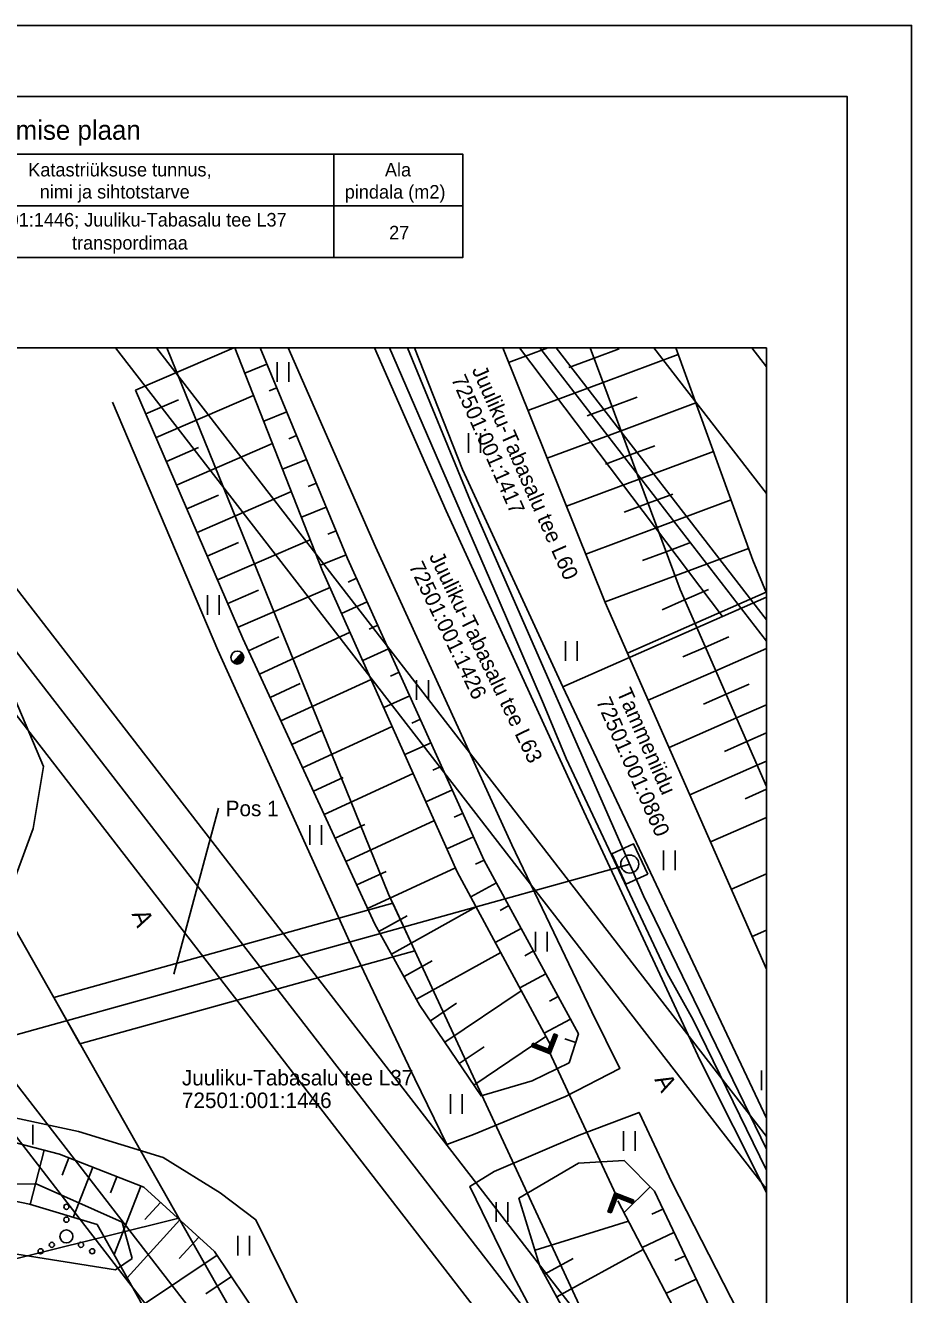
# Model space of a CAD drawing. Extents: x 533279.3 to 533331.8, y 6581483.1 to 6581557.3.
# Drawn here: x 533297.45 to 533331.79, y 6581508.13 to 6581557.32 of the extents above; entities that cross this region are included whole.
import ezdxf

# ---------------------------------------------------------------- set-up
doc = ezdxf.new("R2010")
doc.units = 0
for name, color, linetype in [('HALJASTUS', 7, 'Continuous'), ('KASUTUSALA', 7, 'Continuous'), ('MPKAABEL', 7, 'Continuous'), ('PIIR', 7, 'Continuous'), ('POST', 7, 'Continuous'), ('PR_SIDE', 7, 'Continuous'), ('RELJEEF', 7, 'Continuous'), ('RP-nõlv', 7, 'Continuous'), ('RP-tee_servajoon', 7, 'Continuous'), ('RP-telg_tee', 7, 'Continuous'), ('SITRASS', 7, 'Continuous'), ('TEE', 7, 'Continuous'), ('TRUUP', 7, 'Continuous'), ('VORMISTUS', 7, 'Continuous')]:
    doc.layers.add(name, color=color, linetype=linetype)

msp = doc.modelspace()

# ---------------------------------------------------------------- linework, layer by layer
at = {"layer": 'HALJASTUS'}
for p, q in [((533307.211, 6581544.271), (533307.211, 6581543.51)), ((533307.666, 6581544.271), (533307.666, 6581543.51)), ((533314.628, 6581541.515), (533314.628, 6581540.754)), ((533315.083, 6581541.515), (533315.083, 6581540.754)), ((533304.51, 6581535.234), (533304.51, 6581534.473)), ((533304.966, 6581535.234), (533304.966, 6581534.473)), ((533318.384, 6581533.45), (533318.384, 6581532.689)), ((533318.839, 6581533.45), (533318.839, 6581532.689)), ((533312.613, 6581531.94), (533312.613, 6581531.179)), ((533313.068, 6581531.94), (533313.068, 6581531.179)), ((533308.477, 6581526.324), (533308.477, 6581525.563)), ((533308.932, 6581526.324), (533308.932, 6581525.563)), ((533322.182, 6581525.342), (533322.182, 6581524.581)), ((533322.637, 6581525.342), (533322.637, 6581524.581)), ((533317.213, 6581522.185), (533317.213, 6581521.424)), ((533317.668, 6581522.185), (533317.668, 6581521.424)), ((533325.98, 6581516.812), (533325.98, 6581516.051)), ((533313.921, 6581515.893), (533313.921, 6581515.132)), ((533314.376, 6581515.893), (533314.376, 6581515.132)), ((533297.739, 6581514.711), (533297.739, 6581513.95)), ((533320.631, 6581514.458), (533320.631, 6581513.697)), ((533321.086, 6581514.458), (533321.086, 6581513.697)), ((533315.693, 6581511.713), (533315.693, 6581510.952)), ((533316.148, 6581511.713), (533316.148, 6581510.952)), ((533305.681, 6581510.404), (533305.681, 6581509.643)), ((533306.137, 6581510.404), (533306.137, 6581509.643))]:
    msp.add_line(p, q, dxfattribs=at)
msp.add_lwpolyline([(533301.596, 6581509.531), (533301.205, 6581510.943), (533297.872, 6581512.419), (533293.85, 6581512.397), (533292.416, 6581511.385), (533293.032, 6581509.744), (533296.798, 6581509.751), (533300.946, 6581509.084), (533301.596, 6581509.531)], dxfattribs=at)
for centre, radius in [((533299.042, 6581511.534), 0.1), ((533299.042, 6581511.034), 0.1), ((533299.042, 6581510.384), 0.25), ((533298.477, 6581510.059), 0.1), ((533299.607, 6581510.059), 0.1), ((533298.042, 6581509.809), 0.1), ((533300.042, 6581509.809), 0.1)]:
    msp.add_circle(centre, radius, dxfattribs=at)
at = {"layer": 'KASUTUSALA'}
msp.add_lwpolyline([(533311.685, 6581523.295), (533312.538, 6581521.458), (533299.566, 6581517.847), (533298.55, 6581519.64)], close=True, dxfattribs=at)
at = {"layer": 'MPKAABEL'}
msp.add_lwpolyline([(533311.563, 6581544.821), (533315.768, 6581535.104), (533317.532, 6581531.021), (533318.413, 6581528.914), (533322.317, 6581520.59), (533323.335, 6581518.773), (533326.169, 6581512.95)], dxfattribs=at)
at = {"layer": 'PIIR'}
for points in [[(533314.039, 6581492.321), (533303.4, 6581511.09), (533294.3, 6581527.13), (533291.41, 6581534.01), (533286.879, 6581544.821)], [(533326.169, 6581494.414), (533319, 6581507.54), (533311.52, 6581523.65), (533302.938, 6581544.821)], [(533302.938, 6581544.821), (533311.52, 6581523.65), (533319, 6581507.54), (533326.169, 6581494.414)], [(533316.594, 6581544.821), (533324.47, 6581534.41), (533318.28, 6581531.69), (533314.39, 6581540.11), (533312.531, 6581544.821)], [(533312.531, 6581544.821), (533314.39, 6581540.11), (533318.28, 6581531.69), (533326.169, 6581514.964)], [(533326.169, 6581535.157), (533324.47, 6581534.41), (533316.594, 6581544.821)], [(533326.169, 6581535.157), (533324.47, 6581534.41), (533318.28, 6581531.69), (533326.169, 6581514.964)], [(533284.919, 6581532.5), (533291.41, 6581534.01), (533294.3, 6581527.13), (533303.4, 6581511.09), (533289.68, 6581507.68), (533284.919, 6581513.462)], [(533301.868, 6581492.321), (533289.68, 6581507.68), (533303.4, 6581511.09), (533314.039, 6581492.321)]]:
    msp.add_lwpolyline(points, dxfattribs=at)
at = {"layer": 'POST'}
msp.add_line((533305.487, 6581532.643), (533305.84, 6581532.997), dxfattribs=at)
msp.add_circle((533305.664, 6581532.82), 0.25, dxfattribs=at)
for radius, start, end in [(0.225, 224.8541, 45.0356), (0.2, 224.8427, 45.047), (0.175, 224.8281, 45.0616), (0.15, 224.8087, 45.081), (0.125, 224.7814, 45.1083), (0.1, 224.7406, 45.1491), (0.075, 224.6725, 45.2172), (0.05, 224.5363, 45.3534), (0.025, 224.1278, 45.7619)]:
    msp.add_arc((533305.664, 6581532.82), radius, start, end, dxfattribs=at)
at = {"layer": 'PR_SIDE'}
msp.add_line((533284.919, 6581514.808), (533320.872, 6581524.815), dxfattribs=at)
msp.add_lwpolyline([(533321.567, 6581524.419), (533321.023, 6581525.6), (533320.178, 6581525.212), (533320.722, 6581524.031)], close=True, dxfattribs=at)
msp.add_circle((533320.872, 6581524.815), 0.35, dxfattribs=at)
at = {"layer": 'RELJEEF'}
for p, q in [((533301.723, 6581543.178), (533305.525, 6581544.821)), ((533317.696, 6581544.821), (533316.178, 6581544.257)), ((533319.488, 6581544.421), (533320.463, 6581544.784)), ((533319.837, 6581543.484), (533322.753, 6581544.569)), ((533306.813, 6581544.197), (533305.955, 6581543.841)), ((533319.488, 6581544.421), (533318.509, 6581544.057)), ((533307.196, 6581543.273), (533306.905, 6581543.152)), ((533319.837, 6581543.484), (533316.925, 6581542.401)), ((533302.12, 6581542.26), (533303.39, 6581542.809)), ((533302.517, 6581541.343), (533306.295, 6581542.976)), ((533320.185, 6581542.547), (533319.223, 6581542.189)), ((533320.185, 6581542.547), (533321.155, 6581542.907)), ((533320.534, 6581541.609), (533323.434, 6581542.688)), ((533307.579, 6581542.349), (533306.687, 6581541.979)), ((533320.534, 6581541.609), (533317.673, 6581540.545)), ((533303.31, 6581539.507), (533307.028, 6581541.114)), ((533307.963, 6581541.426), (533307.66, 6581541.3)), ((533302.914, 6581540.425), (533304.163, 6581540.965)), ((533320.883, 6581540.672), (533319.937, 6581540.32)), ((533320.883, 6581540.672), (533321.847, 6581541.031)), ((533321.231, 6581539.735), (533324.115, 6581540.808)), ((533308.346, 6581540.502), (533307.42, 6581540.118)), ((533308.729, 6581539.578), (533308.414, 6581539.448)), ((533321.231, 6581539.735), (533318.42, 6581538.689)), ((533303.707, 6581538.589), (533304.936, 6581539.12)), ((533304.104, 6581537.671), (533307.761, 6581539.251)), ((533321.58, 6581538.798), (533322.539, 6581539.154)), ((533309.112, 6581538.654), (533308.152, 6581538.256)), ((533321.58, 6581538.798), (533320.651, 6581538.452)), ((533321.929, 6581537.86), (533324.796, 6581538.927)), ((533309.495, 6581537.731), (533309.169, 6581537.596)), ((533321.929, 6581537.86), (533319.168, 6581536.833)), ((533304.5, 6581536.753), (533305.709, 6581537.275)), ((533304.897, 6581535.835), (533308.493, 6581537.389)), ((533322.277, 6581536.923), (533323.23, 6581537.278)), ((533309.878, 6581536.807), (533308.884, 6581536.395)), ((533322.277, 6581536.923), (533321.365, 6581536.584)), ((533322.626, 6581535.986), (533325.477, 6581537.047)), ((533310.286, 6581535.894), (533309.957, 6581535.745)), ((533322.626, 6581535.986), (533319.915, 6581534.977)), ((533305.294, 6581534.917), (533306.482, 6581535.431)), ((533305.691, 6581533.999), (533309.257, 6581535.54)), ((533322.998, 6581535.058), (533323.923, 6581535.464)), ((533323.399, 6581534.142), (533326.157, 6581535.351)), ((533310.698, 6581534.983), (533309.707, 6581534.534)), ((533322.998, 6581535.058), (533322.126, 6581534.676)), ((533306.518, 6581532.179), (533310.034, 6581533.802)), ((533311.111, 6581534.072), (533310.779, 6581533.922)), ((533323.399, 6581534.142), (533320.785, 6581532.996)), ((533306.099, 6581533.086), (533307.275, 6581533.629)), ((533323.801, 6581533.226), (533322.93, 6581532.844)), ((533323.801, 6581533.226), (533324.714, 6581533.627)), ((533311.523, 6581533.161), (533310.523, 6581532.708)), ((533324.202, 6581532.31), (533326.169, 6581533.172)), ((533311.936, 6581532.25), (533311.601, 6581532.099)), ((533324.202, 6581532.31), (533321.59, 6581531.165)), ((533306.938, 6581531.271), (533308.106, 6581531.81)), ((533307.357, 6581530.363), (533310.85, 6581531.976)), ((533324.604, 6581531.395), (533325.505, 6581531.79)), ((533312.348, 6581531.339), (533311.34, 6581530.883)), ((533324.604, 6581531.395), (533323.733, 6581531.013)), ((533325.005, 6581530.479), (533326.169, 6581530.989)), ((533312.761, 6581530.428), (533312.423, 6581530.275)), ((533325.005, 6581530.479), (533322.395, 6581529.334)), ((533307.776, 6581529.455), (533308.937, 6581529.991)), ((533308.196, 6581528.547), (533311.667, 6581530.15)), ((533325.407, 6581529.563), (533326.169, 6581529.897)), ((533313.173, 6581529.517), (533312.156, 6581529.057)), ((533325.407, 6581529.563), (533324.537, 6581529.181)), ((533325.808, 6581528.647), (533326.169, 6581528.805)), ((533309.034, 6581526.731), (533312.484, 6581528.325)), ((533313.585, 6581528.606), (533313.245, 6581528.452)), ((533325.808, 6581528.647), (533323.199, 6581527.503)), ((533308.615, 6581527.639), (533309.768, 6581528.172)), ((533313.998, 6581527.695), (533312.973, 6581527.231)), ((533326.169, 6581527.713), (533325.34, 6581527.35)), ((533309.454, 6581525.824), (533310.6, 6581526.353)), ((533309.873, 6581524.916), (533313.3, 6581526.499)), ((533314.41, 6581526.784), (533314.067, 6581526.629)), ((533326.169, 6581526.621), (533324.004, 6581525.672)), ((533314.823, 6581525.873), (533313.789, 6581525.405)), ((533326.169, 6581525.529), (533326.144, 6581525.519)), ((533315.235, 6581524.962), (533314.89, 6581524.806)), ((533310.292, 6581524.008), (533311.431, 6581524.534)), ((533310.711, 6581523.1), (533314.117, 6581524.673)), ((533326.169, 6581524.438), (533324.809, 6581523.841)), ((533315.712, 6581524.083), (533314.712, 6581523.541)), ((533311.638, 6581521.329), (533314.921, 6581523.154)), ((533316.189, 6581523.204), (533315.855, 6581523.023)), ((533311.153, 6581522.203), (533312.251, 6581522.814)), ((533316.666, 6581522.325), (533315.661, 6581521.78)), ((533326.169, 6581522.254), (533325.613, 6581522.01)), ((533312.61, 6581519.581), (533315.87, 6581521.393)), ((533317.143, 6581521.447), (533316.807, 6581521.264)), ((533312.124, 6581520.455), (533313.215, 6581521.061)), ((533317.62, 6581520.568), (533316.61, 6581520.019)), ((533313.708, 6581517.91), (533316.67, 6581519.907)), ((533313.149, 6581518.74), (533314.164, 6581519.423)), ((533318.097, 6581519.689), (533317.759, 6581519.505)), ((533318.574, 6581518.81), (533317.558, 6581518.259)), ((533314.825, 6581516.252), (533317.623, 6581518.137)), ((533318.778, 6581517.906), (533318.362, 6581518.042)), ((533314.266, 6581517.081), (533315.227, 6581517.728)), ((533298.181, 6581513.725), (533297.636, 6581511.626)), ((533299.134, 6581513.43), (533298.871, 6581512.758)), ((533300.065, 6581513.065), (533299.305, 6581511.124)), ((533300.996, 6581512.7), (533300.749, 6581512.068)), ((533301.927, 6581512.336), (533300.887, 6581509.679)), ((533321.661, 6581512.301), (533320.644, 6581511.304)), ((533302.691, 6581511.701), (533302.086, 6581511.035)), ((533322.154, 6581511.442), (533321.732, 6581511.241)), ((533303.431, 6581511.029), (533301.391, 6581508.784)), ((533317.202, 6581509.848), (533320.818, 6581510.97)), ((533304.172, 6581510.356), (533303.416, 6581509.525)), ((533322.584, 6581510.54), (533321.35, 6581509.952)), ((533304.879, 6581509.656), (533301.985, 6581507.715)), ((533318.043, 6581508.043), (533321.391, 6581509.872)), ((533323.014, 6581509.637), (533322.613, 6581509.446)), ((533317.564, 6581508.921), (533318.685, 6581509.534)), ((533305.436, 6581508.825), (533304.443, 6581508.16)), ((533323.443, 6581508.734), (533322.276, 6581508.178))]:
    msp.add_line(p, q, dxfattribs=at)
for points in [[(533301.723, 6581543.178), (533305.883, 6581533.554), (533310.992, 6581522.492), (533312.743, 6581519.341), (533315.111, 6581515.828), (533317.088, 6581516.41), (533318.52, 6581517.115), (533318.885, 6581518.236), (533315.236, 6581524.96), (533309.937, 6581536.665), (533306.554, 6581544.821)], [(533317.816, 6581517.779), (533314.186, 6581524.519), (533308.956, 6581536.213), (533305.569, 6581544.821)], [(533315.95, 6581544.821), (533319.924, 6581534.957), (533326.169, 6581520.747)], [(533319.339, 6581544.821), (533322.824, 6581535.454), (533326.169, 6581527.824)], [(533322.661, 6581544.821), (533325.642, 6581536.592), (533326.169, 6581535.322)], [(533284.919, 6581513.429), (533287.357, 6581513.757), (533292.718, 6581514.44), (533295.532, 6581514.413), (533298.77, 6581513.572), (533302.044, 6581512.29), (533304.781, 6581509.803), (533308.425, 6581504.368), (533311.925, 6581498.098)], [(533326.169, 6581503.075), (533324.818, 6581505.846), (533321.825, 6581512.134), (533320.659, 6581513.322), (533318.883, 6581513.228), (533316.576, 6581511.865), (533317.392, 6581509.235), (533322.569, 6581499.759)], [(533284.919, 6581512.096), (533287.494, 6581512.216), (533293.014, 6581512.587), (533297.606, 6581511.635), (533300.228, 6581510.847), (533301.844, 6581507.98), (533304.308, 6581503.346), (533307.513, 6581497.59)], [(533326.169, 6581500.695), (533323.749, 6581505.354), (533320.405, 6581511.761)]]:
    msp.add_lwpolyline(points, dxfattribs=at)
at = {"layer": 'RP-nõlv'}
for p, q in [((533326.169, 6581514.255), (533302.527, 6581544.821)), ((533326.169, 6581533.461), (533317.382, 6581544.821)), ((533314.056, 6581492.321), (533284.919, 6581529.994))]:
    msp.add_line(p, q, dxfattribs=at)
at = {"layer": 'RP-tee_servajoon'}
for p, q in [((533326.169, 6581493.006), (533286.093, 6581544.821)), ((533326.169, 6581497.91), (533289.885, 6581544.821)), ((533326.169, 6581512.212), (533300.947, 6581544.821)), ((533326.169, 6581534.278), (533318.014, 6581544.821)), ((533326.169, 6581544.085), (533325.599, 6581544.821)), ((533315.637, 6581492.321), (533284.919, 6581532.037))]:
    msp.add_line(p, q, dxfattribs=at)
at = {"layer": 'RP-telg_tee'}
for p, q in [((533326.169, 6581495.458), (533287.989, 6581544.821)), ((533326.169, 6581539.181), (533321.807, 6581544.821))]:
    msp.add_line(p, q, dxfattribs=at)
at = {"layer": 'SITRASS'}
msp.add_lwpolyline([(533312.261, 6581544.821), (533314.701, 6581538.877), (533321.41, 6581523.582), (533326.169, 6581513.771)], dxfattribs=at)
at = {"layer": 'TEE'}
for points in [[(533300.834, 6581542.715), (533304.915, 6581533.103), (533309.953, 6581521.952), (533312.545, 6581516.498), (533313.78, 6581513.945), (533314.812, 6581514.331), (533318.385, 6581515.808), (533320.487, 6581516.887), (533319.399, 6581519.093), (533316.302, 6581525.558), (533311.019, 6581537.113), (533307.641, 6581544.821)], [(533326.169, 6581512.083), (533323.599, 6581517.205), (533319.091, 6581526.86), (533313.759, 6581538.502), (533310.983, 6581544.821)], [(533284.919, 6581518.853), (533286.115, 6581519.072), (533291.163, 6581519.939), (533294.36, 6581521.188), (533296.727, 6581523.417), (533297.752, 6581526.189), (533298.149, 6581528.6), (533294.521, 6581537.152)], [(533312.852, 6581498.482), (533309.623, 6581504.459), (533306.388, 6581511.03), (533305.005, 6581512.072), (533302.788, 6581513.446), (533299.515, 6581514.457), (533295.949, 6581515.216), (533292.859, 6581515.08), (533287.545, 6581514.499), (533284.919, 6581514.072)], [(533326.169, 6581505.38), (533325.649, 6581506.325), (533322.502, 6581512.484), (533321.231, 6581515.194), (533318.912, 6581514.304), (533315.616, 6581512.897), (533314.671, 6581512.318), (533316.354, 6581508.865), (533321.528, 6581499.114)]]:
    msp.add_lwpolyline(points, dxfattribs=at)
at = {"layer": 'TRUUP'}
for p, q in [((533317.706, 6581517.646), (533317.937, 6581518.238)), ((533317.747, 6581517.554), (533318.003, 6581518.212)), ((533317.787, 6581517.461), (533318.07, 6581518.187)), ((533317.823, 6581517.946), (533317.93, 6581517.828)), ((533317.833, 6581517.972), (533317.94, 6581517.854)), ((533317.843, 6581517.998), (533317.95, 6581517.88)), ((533317.854, 6581518.024), (533317.96, 6581517.906)), ((533317.864, 6581518.05), (533317.97, 6581517.932)), ((533317.874, 6581518.077), (533317.981, 6581517.958)), ((533317.884, 6581518.103), (533317.991, 6581517.984)), ((533317.894, 6581518.129), (533318.001, 6581518.01)), ((533317.904, 6581518.155), (533318.011, 6581518.036)), ((533317.915, 6581518.181), (533318.021, 6581518.062)), ((533317.925, 6581518.207), (533318.031, 6581518.088)), ((533317.935, 6581518.233), (533318.042, 6581518.114)), ((533317.937, 6581518.238), (533318.07, 6581518.187)), ((533317.978, 6581518.222), (533318.052, 6581518.141)), ((533318.03, 6581518.202), (533318.062, 6581518.167)), ((533317.114, 6581517.877), (533317.062, 6581517.744)), ((533317.062, 6581517.744), (533317.787, 6581517.461)), ((533317.073, 6581517.771), (533317.116, 6581517.723)), ((533317.083, 6581517.797), (533317.168, 6581517.703)), ((533317.088, 6581517.81), (533317.747, 6581517.554)), ((533317.093, 6581517.823), (533317.22, 6581517.682)), ((533317.103, 6581517.85), (533317.272, 6581517.662)), ((533317.113, 6581517.876), (533317.323, 6581517.642)), ((533317.114, 6581517.877), (533317.706, 6581517.646)), ((533317.163, 6581517.857), (533317.375, 6581517.622)), ((533317.215, 6581517.837), (533317.427, 6581517.602)), ((533317.267, 6581517.817), (533317.479, 6581517.582)), ((533317.319, 6581517.797), (533317.53, 6581517.561)), ((533317.371, 6581517.776), (533317.582, 6581517.541)), ((533317.422, 6581517.756), (533317.634, 6581517.521)), ((533317.474, 6581517.736), (533317.686, 6581517.501)), ((533317.526, 6581517.716), (533317.737, 6581517.481)), ((533317.578, 6581517.696), (533317.787, 6581517.462)), ((533317.629, 6581517.676), (533317.798, 6581517.488)), ((533317.681, 6581517.655), (533317.808, 6581517.515)), ((533317.711, 6581517.659), (533317.818, 6581517.541)), ((533317.722, 6581517.685), (533317.828, 6581517.567)), ((533317.732, 6581517.711), (533317.838, 6581517.593)), ((533317.742, 6581517.737), (533317.848, 6581517.619)), ((533320.34, 6581511.979), (533317.747, 6581517.554)), ((533317.752, 6581517.764), (533317.859, 6581517.645)), ((533317.762, 6581517.79), (533317.869, 6581517.671)), ((533317.772, 6581517.816), (533317.879, 6581517.697)), ((533317.783, 6581517.842), (533317.889, 6581517.723)), ((533317.793, 6581517.868), (533317.899, 6581517.749)), ((533317.803, 6581517.894), (533317.909, 6581517.775)), ((533317.813, 6581517.92), (533317.92, 6581517.801)), ((533320.299, 6581512.071), (533320.02, 6581511.344)), ((533320.458, 6581511.857), (533320.289, 6581512.044)), ((533321.026, 6581511.791), (533320.299, 6581512.071)), ((533320.51, 6581511.837), (533320.299, 6581512.07)), ((533320.562, 6581511.817), (533320.349, 6581512.052)), ((533320.614, 6581511.797), (533320.401, 6581512.032)), ((533320.34, 6581511.979), (533320.087, 6581511.319)), ((533320.205, 6581511.429), (533320.098, 6581511.547)), ((533320.215, 6581511.455), (533320.108, 6581511.573)), ((533320.225, 6581511.481), (533320.118, 6581511.599)), ((533320.235, 6581511.507), (533320.128, 6581511.626)), ((533320.245, 6581511.534), (533320.138, 6581511.652)), ((533320.255, 6581511.56), (533320.148, 6581511.678)), ((533320.381, 6581511.887), (533320.153, 6581511.293)), ((533320.265, 6581511.586), (533320.158, 6581511.704)), ((533320.276, 6581511.612), (533320.168, 6581511.73)), ((533320.286, 6581511.638), (533320.178, 6581511.756)), ((533320.296, 6581511.664), (533320.188, 6581511.782)), ((533320.306, 6581511.69), (533320.199, 6581511.808)), ((533320.316, 6581511.717), (533320.209, 6581511.835)), ((533320.326, 6581511.743), (533320.219, 6581511.861)), ((533320.336, 6581511.769), (533320.229, 6581511.887)), ((533320.346, 6581511.795), (533320.239, 6581511.913)), ((533320.356, 6581511.821), (533320.249, 6581511.939)), ((533320.366, 6581511.847), (533320.259, 6581511.965)), ((533320.376, 6581511.873), (533320.269, 6581511.991)), ((533320.406, 6581511.877), (533320.279, 6581512.017)), ((533321, 6581511.725), (533320.34, 6581511.979)), ((533320.975, 6581511.659), (533320.381, 6581511.887)), ((533320.665, 6581511.777), (533320.453, 6581512.012)), ((533320.717, 6581511.758), (533320.505, 6581511.992)), ((533320.769, 6581511.738), (533320.557, 6581511.972)), ((533320.821, 6581511.718), (533320.608, 6581511.952)), ((533320.873, 6581511.698), (533320.66, 6581511.932)), ((533320.925, 6581511.678), (533320.712, 6581511.912)), ((533320.975, 6581511.66), (533320.764, 6581511.892)), ((533320.985, 6581511.686), (533320.816, 6581511.872)), ((533320.995, 6581511.712), (533320.868, 6581511.852)), ((533321.005, 6581511.738), (533320.92, 6581511.832)), ((533321.015, 6581511.764), (533320.971, 6581511.812)), ((533320.975, 6581511.659), (533321.026, 6581511.791)), ((533320.153, 6581511.293), (533320.02, 6581511.344)), ((533320.06, 6581511.329), (533320.028, 6581511.364)), ((533320.111, 6581511.309), (533320.038, 6581511.39)), ((533320.155, 6581511.298), (533320.048, 6581511.416)), ((533320.165, 6581511.325), (533320.058, 6581511.443)), ((533320.175, 6581511.351), (533320.068, 6581511.469)), ((533320.185, 6581511.377), (533320.078, 6581511.495)), ((533320.195, 6581511.403), (533320.088, 6581511.521))]:
    msp.add_line(p, q, dxfattribs=at)
at = {"layer": 'VORMISTUS'}
for p, q in [((533309.405, 6581552.326), (533309.405, 6581548.326)), ((533284.905, 6581550.326), (533314.405, 6581550.326)), ((533303.2, 6581520.543), (533304.938, 6581526.984))]:
    msp.add_line(p, q, dxfattribs=at)
for points in [[(533279.294, 6581557.321), (533331.794, 6581557.321), (533331.794, 6581483.071), (533279.294, 6581483.071)], [(533281.794, 6581485.821), (533329.294, 6581485.821), (533329.294, 6581554.571), (533281.794, 6581554.571)], [(533281.794, 6581554.571), (533329.294, 6581554.571), (533329.294, 6581485.821), (533281.794, 6581485.821)], [(533284.905, 6581552.326), (533314.405, 6581552.326), (533314.405, 6581548.326), (533284.905, 6581548.326)], [(533326.169, 6581492.321), (533284.919, 6581492.321), (533284.919, 6581544.821), (533326.169, 6581544.821)]]:
    msp.add_lwpolyline(points, close=True, dxfattribs=at)

# ---------------------------------------------------------------- texts
at = {"layer": 'PIIR'}
for s, rotation, p in [('Juuliku-Tabasalu tee L60', 293.7631, (533314.741, 6581543.974)), ('72501:001:1417', 293.7631, (533313.94, 6581543.621)), ('Juuliku-Tabasalu tee L63', 295.7482, (533313.083, 6581536.744)), ('72501:001:1426', 295.7482, (533312.295, 6581536.364)), ('Tammeniidu', 293.8665, (533320.353, 6581531.48)), ('72501:001:0860', 293.8665, (533319.553, 6581531.126))]:
    msp.add_text(s, height=0.6, rotation=rotation, dxfattribs=at).set_placement(p)
for s, p in [('Juuliku-Tabasalu tee L37', (533303.518, 6581516.236)), ('72501:001:1446', (533303.518, 6581515.361))]:
    msp.add_text(s, height=0.6, dxfattribs=at).set_placement(p)
at = {"layer": 'TEE'}
for rotation, p in [(292.1583, (533301.559, 6581522.886)), (297.3734, (533321.816, 6581516.466))]:
    msp.add_text('A', height=0.7, rotation=rotation, dxfattribs=at).set_placement(p)
at = {"layer": 'VORMISTUS'}
for s, height, p in [('Isikliku kasutusõiguse seadmise plaan', 0.75, (533284.921, 6581552.889)), ('Katastriüksuse tunnus,', 0.525, (533297.563, 6581551.467)), ('Ala', 0.525, (533311.384, 6581551.467)), ('nimi ja sihtotstarve', 0.525, (533298.008, 6581550.612)), ('pindala (m2)', 0.525, (533309.828, 6581550.608)), ('72501:001:1446; Juuliku-Tabasalu tee L37', 0.525, (533294.266, 6581549.526)), ('27', 0.525, (533311.547, 6581549.026)), ('transpordimaa', 0.525, (533299.259, 6581548.633)), ('Pos 1', 0.6, (533305.214, 6581526.672))]:
    msp.add_text(s, height=height, dxfattribs=at).set_placement(p)

doc.saveas('drawing.dxf')
